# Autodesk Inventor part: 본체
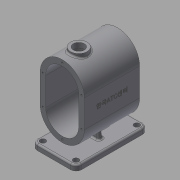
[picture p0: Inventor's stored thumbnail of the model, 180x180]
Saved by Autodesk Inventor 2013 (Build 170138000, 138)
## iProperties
Created: 2016-12
Part Number: 본체
Material: 일반
Document SubType Name: Modeling
Designer: mduedu
Density: 1 g/cm^3
Author: mduedu
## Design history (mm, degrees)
sketch "스케치1"
  geometry: L1 (40, -25)-(40, 25); L2 (-40, 25)-(-40, -25); L3 (-40, -25)-(40, 25); L4 (40, -25)-(-40, 25); L5 (0, 25)-(0, -25); A1 r 40 centre (0, 25) between (40, 25) and (-40, 25); A2 r 40 centre (0, -25) between (-40, -25) and (40, -25); 1 further point
  constraints: 10 end point, 4 point on circle, 3 tangent, 2 centre point, 2 midpoint, 2 parallel, 1 vertical
  dimensions: "d0" = 130 dimension on A2 A1; "d2" = 80 distance between parallel lines of L1 L2
extrude "돌출1" new body sketch "스케치1" stored distance "d3" = 100; taper "d4" = 0 deg
feature "쉘1" dims "d5" = 10
sketch "스케치2"
  geometry: L1 (-75, 65)-(-85, 65); L2 (-85, 65)-(-85, -65); L3 (-85, -65)-(-75, -65); L4 (-75, -65)-(-75, 65); 2 further points
  constraints: 8 end point, 2 parallel, 1 horizontal, 1 horizontal alignment, 1 midpoint, 1 perpendicular
  dimensions: "d6" = 85 distance from line of L2 point (0, 0); "d7" = 130 distance of L1.end L2.end; "d8" = 10 distance of L2.end L3.end
extrude "돌출2" join sketch "스케치2" stored distance "d9" = 80; taper "d10" = 0 deg
fillet "모깎기1" dims "d11" = 10
sketch "스케치3"
  geometry: L1 (-10, 10)-(-10, 120) reference; L2 (60, 0)-(0, 0) reference; L3 (70, 120)-(70, 10) reference; L4 (0, 130)-(60, 130) reference; A1 r 10 centre (0, 120) between (0, 130) and (-10, 120) reference; A2 r 10 centre (0, 10) between (-10, 10) and (0, 0) reference; A3 r 10 centre (60, 10) between (60, 0) and (70, 10) reference; A4 r 10 centre (60, 120) between (70, 120) and (60, 130) reference; 5 further points
  constraints: 4 coincident
hole "구멍1" sketch "스케치3" at (60, 120), (60, 10), (0, 10), (0, 120) diameter "d12" = 10; stored, may be unused: countersink angle "d16" = 90 deg, drill point angle "d18" = 118 deg; dims "d13" = 6, "d14" = 4, "d15" = 2, "d17" = 8
sketch "스케치5"
  geometry: L1 (34, 35)-(26, 35); L2 (26, 35)-(26, 95); L3 (26, 95)-(34, 95); L4 (34, 95)-(34, 35); L5 (34, 35)-(26, 95); L6 (26, 35)-(34, 95); 1 further point
  constraints: 12 end point, 2 midpoint, 2 parallel, 1 horizontal, 1 perpendicular
  dimensions: "d22" = 8 distance of L2.end L3.end; "d24" = 60 distance of L1.end L2.end
extrude "돌출3" join sketch "스케치5" stored distance "d25" = 80; taper "d26" = 0 deg
feature "면 기울기1" dims angle "d27" = 5 deg
sketch "스케치6"
  geometry: L1 (-30, -75)-(30, -75) reference; L2 (-17.524, -60.957)-(-20, -75); A1 r 40 centre (0, -25) between (-40, -25) and (40, -25) reference; 1 further point
  constraints: 2 end point, 1 point on circle, 1 point on line
  dimensions: "d28" = 20 horizontal distance of A1.centre L2.end; "d29" = 80 deg angle of L2 L1
feature "리브1" sketch "스케치6" dims "d30" = 1, "d31" = 8, "d32" = 0, "d33" = 0, "d34" = 1, "d35" = 1
fillet "모깎기2" dims "d36" = 3
fillet "모깎기3" dims "d37" = 3, "d38" = 3
node "작업 평면1"
sketch "스케치9"
  geometry: 1 further point
sketch "스케치7"
  geometry: L1 (40, 50)-(-40, 50) reference; C1 r 15 at (0, 20); 1 further point
  constraints: 1 centre point, 1 vertical alignment
  dimensions: "d40" = 30 diameter of C1; "d41" = 30 distance from line of C1.centre L1
extrude "돌출4" join sketch "스케치7" stored distance "d42" = 80; taper "d43" = 0 deg
hole "구멍2" diameter "d46" = 20; stored, may be unused: countersink angle "d50" = 90 deg, drill point angle "d52" = 118 deg; dims "d44" = 10, "d45" = 10, "d47" = 6, "d48" = 4, "d49" = 2, "d51" = 8
fillet "모깎기4" dims "d53" = 3
node "작업 평면2"
sketch "스케치8"
  geometry: C1 r 15 at (0, 0) reference; C2 r 15 at (0, 0); 1 further point
  constraints: 1 centre point, 1 coincident
  dimensions: "d55" = 30 diameter of C2
extrude "돌출5" cut sketch "스케치8" stored distance "d56" = 80; taper "d57" = 0 deg
chamfer "모따기1" distance "d58" = 1; stored, may be unused: second distance "d59" = 2, angle "d60" = 45 deg
sketch "스케치10"
  geometry: 2 further points
  constraints: 1 coincident, 1 other
feature "엠보싱1" sketch "스케치10" dims "d0" = 130, "d2" = 80, "d61" = 0.5, "d62" = 0
sketch "스케치11"
  geometry: 1 further point
hole "구멍3" sketch "스케치11" at (0, 60) diameter "d63" = 3.242; stored, may be unused: countersink angle "d67" = 90 deg, drill point angle "d69" = 120 deg; dims "d64" = 8.6, "d65" = 4, "d66" = 2, "d68" = 10.6
sketch "스케치12"
  geometry: 1 further point
hole "구멍5" sketch "스케치12" at (0, 60) diameter "d70" = 3.242; stored, may be unused: countersink angle "d74" = 90 deg, drill point angle "d76" = 120 deg; dims "d71" = 8.6, "d72" = 4, "d73" = 2, "d75" = 10.6
node "솔리드1"
mirror "대칭1"
pattern_linear "직사각형 패턴1"
pattern_linear "직사각형 패턴2"
node "투영된 루프1"
sketch "스케치13"
  geometry: L1 (-40, 25)-(-40, -25) reference; L2 (40, -25)-(40, 25) reference; L3 (35, 25)-(35, -25); L4 (-35, -25)-(-35, 25); A1 r 40 centre (0, 25) between (40, 25) and (-40, 25) reference; A2 r 40 centre (0, -25) between (-40, -25) and (40, -25) reference; A3 r 35 centre (0, 25) between (35, 25) and (-35, 25); A4 r 35 centre (0, -25) between (-35, -25) and (35, -25); 2 further points
  constraints: 5 point on circle, 4 end point, 2 centre point, 3 other
  dimensions: "d77" = 5 distance between parallel lines of L3 L2
sketch "스케치14"
  geometry: L1 (-40, 25)-(-40, -25) reference; L2 (40, -25)-(40, 25) reference; L3 (35, 25)-(35, -25); L4 (-35, -25)-(-35, 25); A1 r 40 centre (0, 25) between (40, 25) and (-40, 25) reference; A2 r 40 centre (0, -25) between (-40, -25) and (40, -25) reference; A3 r 35 centre (0, 25) between (35, 25) and (-35, 25); A4 r 35 centre (0, -25) between (-35, -25) and (35, -25); 2 further points
  constraints: 5 point on circle, 4 end point, 2 centre point, 3 other
  dimensions: "d80" = 5 distance between parallel lines of L2 L3
